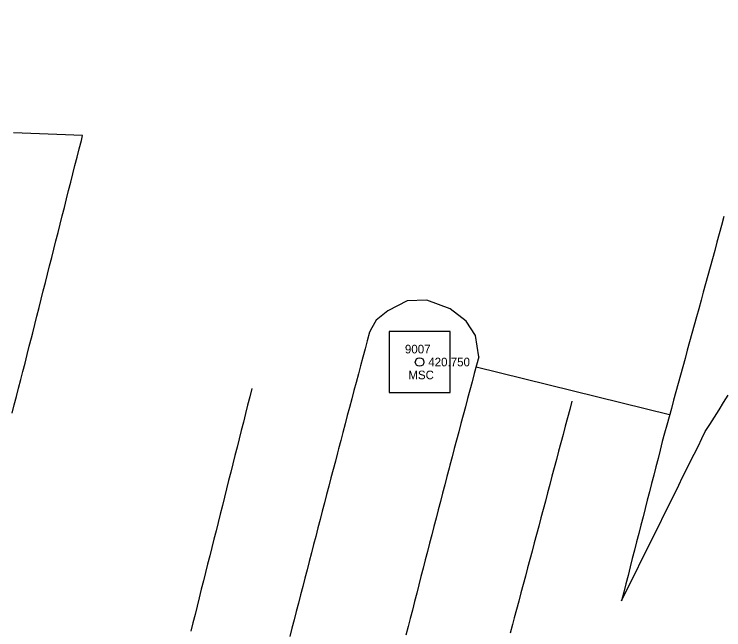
# Model space of a CAD drawing. Extents: x 1901471 to 1963503, y 756461 to 799997.
# Drawn here: x 1929567.1 to 1929649.4, y 772631 to 772702.4 of the extents above; entities that cross this region are included whole.
import ezdxf

# ---------------------------------------------------------------- set-up
doc = ezdxf.new("R2010")
doc.units = 0
for name, color, linetype in [('RD_EX_Road', 7, 'Continuous'), ('RD_EX_Road_txCode', 7, 'Continuous'), ('RD_HC_Cl', 7, 'Continuous'), ('RD_HC_Survey', 7, 'Continuous'), ('RD_HC_txCode', 7, 'Continuous'), ('RD_SMD_Locator', 7, 'Continuous')]:
    doc.layers.add(name, color=color, linetype=linetype)

msp = doc.modelspace()

# ---------------------------------------------------------------- linework, layer by layer
at = {"layer": 'RD_EX_Road'}
for points in [[(1929566.88, 772656.12), (1929567.12, 772657.09), (1929567.37, 772658.06), (1929567.62, 772659.03), (1929567.87, 772660), (1929568.11, 772660.96), (1929568.36, 772661.93), (1929568.61, 772662.9), (1929568.85, 772663.87), (1929569.1, 772664.84), (1929569.25, 772665.44), (1929569.5, 772666.41), (1929569.74, 772667.38), (1929569.99, 772668.35), (1929570.23, 772669.32), (1929570.48, 772670.29), (1929570.72, 772671.26), (1929570.72, 772671.26), (1929570.97, 772672.23), (1929571.21, 772673.2), (1929571.46, 772674.17), (1929571.7, 772675.14), (1929571.95, 772676.11), (1929572.19, 772677.07), (1929572.44, 772678.04), (1929572.68, 772679.01), (1929572.93, 772679.98), (1929573.17, 772680.95), (1929573.42, 772681.92), (1929573.66, 772682.89), (1929573.91, 772683.86), (1929574.15, 772684.83), (1929574.4, 772685.8), (1929574.64, 772686.77), (1929574.89, 772687.74), (1929575.03, 772688.31), (1929574.03, 772688.35), (1929573.04, 772688.39), (1929572.04, 772688.43), (1929571.04, 772688.46), (1929570.04, 772688.5), (1929569.04, 772688.54), (1929568.04, 772688.58), (1929567.04, 772688.62)], [(1929649.4, 772678.93), (1929649.12, 772677.88), (1929648.86, 772676.91), (1929648.59, 772675.95), (1929648.33, 772674.98), (1929648.06, 772674.02), (1929647.8, 772673.06), (1929647.53, 772672.09), (1929647.27, 772671.13), (1929647, 772670.16), (1929646.74, 772669.2), (1929646.47, 772668.23), (1929646.21, 772667.27), (1929645.94, 772666.31), (1929645.68, 772665.34), (1929645.41, 772664.38), (1929645.15, 772663.41), (1929644.89, 772662.45), (1929644.62, 772661.49), (1929644.36, 772660.52), (1929644.09, 772659.56), (1929643.83, 772658.59), (1929643.56, 772657.63), (1929643.3, 772656.66), (1929643.03, 772655.7), (1929642.77, 772654.74), (1929642.5, 772653.78), (1929642.25, 772652.81), (1929642.01, 772651.84), (1929641.76, 772650.87), (1929641.51, 772649.9), (1929641.26, 772648.94), (1929641.01, 772647.97), (1929640.76, 772647), (1929640.51, 772646.03), (1929640.27, 772645.06), (1929640.02, 772644.09), (1929639.77, 772643.12), (1929639.52, 772642.16), (1929639.27, 772641.19), (1929639.02, 772640.22), (1929638.77, 772639.25), (1929638.53, 772638.28), (1929638.28, 772637.31), (1929638.03, 772636.34), (1929637.78, 772635.37), (1929637.52, 772634.34), (1929637.96, 772635.24), (1929638.4, 772636.13), (1929638.85, 772637.03), (1929639.29, 772637.92), (1929639.73, 772638.82), (1929640.18, 772639.72), (1929640.62, 772640.61), (1929641.06, 772641.51), (1929641.51, 772642.41), (1929641.95, 772643.3), (1929642.4, 772644.2), (1929642.4, 772644.2), (1929642.84, 772645.09), (1929643.28, 772645.99), (1929643.73, 772646.89), (1929644.17, 772647.78), (1929644.61, 772648.68), (1929645.06, 772649.57), (1929645.5, 772650.47), (1929645.95, 772651.37), (1929646.39, 772652.26), (1929646.83, 772653.16), (1929647.23, 772653.97), (1929647.76, 772654.81), (1929648.29, 772655.66), (1929648.83, 772656.51), (1929649.36, 772657.36), (1929649.89, 772658.2)], [(1929620.97, 772662.65), (1929620.6, 772665.11), (1929619.52, 772666.78), (1929617.67, 772668.23), (1929614.93, 772669.21), (1929612.66, 772669.13), (1929610.41, 772667.99), (1929609.09, 772666.88), (1929608.58, 772666), (1929608.3, 772665.49)], [(1929608.3, 772665.49), (1929608.04, 772664.52), (1929607.78, 772663.56), (1929607.53, 772662.59), (1929607.27, 772661.62), (1929607.01, 772660.66), (1929606.76, 772659.69), (1929606.5, 772658.73), (1929606.24, 772657.76), (1929605.99, 772656.79), (1929605.73, 772655.83), (1929605.48, 772654.86), (1929605.22, 772653.89), (1929604.96, 772652.93), (1929604.71, 772651.96), (1929604.59, 772651.51), (1929604.34, 772650.54), (1929604.08, 772649.58), (1929603.83, 772648.61), (1929603.58, 772647.64), (1929603.33, 772646.67), (1929603.08, 772645.7), (1929602.83, 772644.74), (1929602.57, 772643.77), (1929602.32, 772642.8), (1929602.07, 772641.83), (1929601.82, 772640.87), (1929601.57, 772639.9), (1929601.32, 772638.93), (1929601.07, 772637.96), (1929600.81, 772636.99), (1929600.56, 772636.03), (1929600.31, 772635.06), (1929600.06, 772634.09), (1929599.81, 772633.12), (1929599.56, 772632.15), (1929599.3, 772631.19), (1929599.05, 772630.22)], [(1929620.97, 772662.65), (1929620.71, 772661.68), (1929620.45, 772660.71), (1929620.19, 772659.75), (1929619.94, 772658.78), (1929619.68, 772657.82), (1929619.42, 772656.85), (1929619.16, 772655.88), (1929618.9, 772654.92), (1929618.64, 772653.95), (1929618.38, 772652.99), (1929618.13, 772652.02), (1929617.87, 772651.05), (1929617.61, 772650.09), (1929617.52, 772649.75), (1929617.27, 772648.78), (1929617.02, 772647.82), (1929616.77, 772646.85), (1929616.52, 772645.88), (1929616.27, 772644.91), (1929616.02, 772643.94), (1929615.77, 772642.97), (1929615.52, 772642.01), (1929615.27, 772641.04), (1929615.02, 772640.07), (1929614.77, 772639.1), (1929614.52, 772638.13), (1929614.27, 772637.17), (1929614.02, 772636.2), (1929613.77, 772635.23), (1929613.52, 772634.26), (1929613.27, 772633.29), (1929613.02, 772632.32), (1929612.77, 772631.36), (1929612.52, 772630.39)], [(1929620.66, 772661.48), (1929643.1, 772655.96)], [(1929594.65, 772658.97), (1929594.41, 772658), (1929594.16, 772657.03), (1929593.92, 772656.06), (1929593.68, 772655.09), (1929593.43, 772654.12), (1929593.19, 772653.15), (1929592.95, 772652.18), (1929592.7, 772651.21), (1929592.46, 772650.24), (1929592.21, 772649.27), (1929591.97, 772648.3), (1929591.73, 772647.33), (1929591.48, 772646.36), (1929591.24, 772645.39), (1929590.99, 772644.42), (1929590.75, 772643.45), (1929590.51, 772642.48), (1929590.26, 772641.51), (1929590.02, 772640.54), (1929589.77, 772639.57), (1929589.53, 772638.6), (1929589.29, 772637.63), (1929589.04, 772636.66), (1929588.8, 772635.69), (1929588.55, 772634.72), (1929588.31, 772633.75), (1929588.07, 772632.78), (1929587.82, 772631.81), (1929587.58, 772630.84)], [(1929631.77, 772657.5), (1929631.52, 772656.54), (1929631.26, 772655.57), (1929631, 772654.61), (1929630.75, 772653.64), (1929630.49, 772652.67), (1929630.23, 772651.71), (1929629.97, 772650.74), (1929629.72, 772649.77), (1929629.46, 772648.81), (1929629.2, 772647.84), (1929628.95, 772646.87), (1929628.69, 772645.91), (1929628.43, 772644.94), (1929628.17, 772643.98), (1929627.92, 772643.01), (1929627.66, 772642.04), (1929627.4, 772641.08), (1929627.15, 772640.11), (1929626.89, 772639.14), (1929626.63, 772638.18), (1929626.38, 772637.21), (1929626.12, 772636.24), (1929625.86, 772635.28), (1929625.6, 772634.31), (1929625.35, 772633.35), (1929625.09, 772632.38), (1929624.88, 772631.59), (1929624.63, 772630.62)]]:
    msp.add_lwpolyline(points, dxfattribs=at)
at = {"layer": 'RD_HC_Cl'}
for centre, radius, start, end in [((1933934.019, 762479.741), 11482.379, 112.0131601, 122.8458902), ((1933920.665, 762509.144), 11420.505, 112.014247, 122.8463779), ((1933910.025, 762523.402), 11373.858, 112.013249, 123.5418878)]:
    msp.add_arc(centre, radius, start, end, dxfattribs=at)
at = {"layer": 'RD_HC_Survey'}
msp.add_lwpolyline([(1929617.651, 772665.582), (1929610.579, 772665.582), (1929610.579, 772658.51), (1929617.651, 772658.51)], close=True, dxfattribs=at)
msp.add_circle((1929614.115, 772662.046), 0.5, dxfattribs=at)
at = {"layer": 'RD_SMD_Locator'}
msp.add_circle((1929614.115, 772662.046), 0.001, dxfattribs=at)

# ---------------------------------------------------------------- texts
at = {"layer": 'RD_EX_Road_txCode'}
msp.add_text('420.750', height=1, dxfattribs=at).set_placement((1929615.115, 772661.546))
at = {"layer": 'RD_HC_txCode'}
for s, p in [('9007', (1929612.406, 772663.046)), ('MSC', (1929612.8, 772660.046))]:
    msp.add_text(s, height=1, dxfattribs=at).set_placement(p)

doc.saveas('drawing.dxf')
